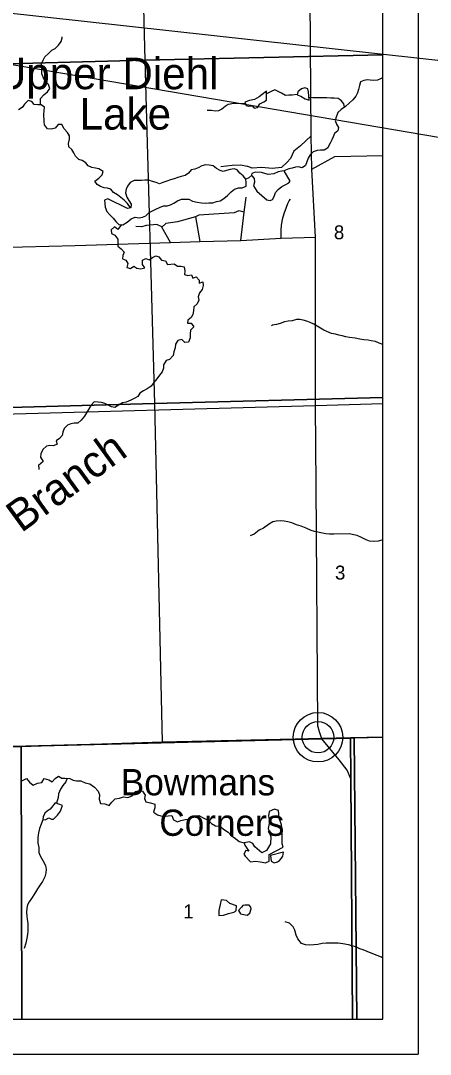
# Model space of a CAD drawing. Extents: x 0 to 34, y 0 to 22.
# Drawn here: x 8.435 to 9.666, y 9.902 to 13.008 of the extents above; entities that cross this region are included whole.
import ezdxf

# ---------------------------------------------------------------- set-up
doc = ezdxf.new("R2010")
doc.units = 0
for name, color, linetype in [('GM_X_Corporation', 7, 'Continuous'), ('GM_X_County_Road', 7, 'Continuous'), ('GM_X_Minor_Lake', 7, 'Continuous'), ('GM_X_Minor_Lake_Text', 7, 'Continuous'), ('GM_X_Minor_River', 7, 'Continuous'), ('GM_X_Minor_River_Text', 7, 'Continuous'), ('GM_X_Section_Text', 7, 'Continuous'), ('GM_X_State_Route', 7, 'Continuous'), ('GM_X_Township_Road', 7, 'Continuous'), ('GM_X_Unincorporated', 7, 'Continuous'), ('GM_X_Unincorporated_Location', 7, 'Continuous'), ('GM_X_Unincorporated_Text', 7, 'Continuous'), ('SH_Data', 7, 'Continuous'), ('SH_Text', 7, 'Continuous')]:
    doc.layers.add(name, color=color, linetype=linetype)

msp = doc.modelspace()

# ---------------------------------------------------------------- linework, layer by layer
at = {"layer": 'GM_X_Corporation'}
msp.add_lwpolyline([(6.7793, 13.0289), (6.7835, 12.8989), (6.7875, 12.7733), (6.7907, 12.6568), (6.7962, 12.4725), (6.8009, 12.313), (6.8013, 12.2922), (6.8061, 11.7851), (6.8093, 11.6831), (6.8339, 10.7907), (7.8767, 10.8135), (8.3328, 10.8251), (9.3392, 10.8506), (9.4256, 10.8527), (9.5231, 10.8551), (9.5231, 15.9621)], dxfattribs=at)
for points in [[(9.5231, 12.905), (9.5231, 13.9277), (8.7817, 13.9109), (8.8081, 12.8893)], [(8.7817, 13.9109), (8.8081, 12.8893), (7.797, 12.8624), (7.775, 13.8905)], [(9.5231, 11.8754), (9.5231, 12.905), (8.8081, 12.8893), (8.8368, 11.8577)], [(8.8081, 12.8893), (8.8368, 11.8577), (7.823, 11.8291), (7.797, 12.8624)], [(9.5231, 10.8546), (9.5231, 11.8754), (8.8368, 11.8577), (8.8598, 10.8393), (9.4367, 10.8525)], [(7.823, 11.8291), (8.8368, 11.8577), (8.8598, 10.8393), (8.4367, 10.8255), (7.8468, 10.813)], [(3.2288, 10.0075), (9.4322, 10.0075), (9.4266, 10.7304), (9.4256, 10.8527), (9.3392, 10.8506), (8.3328, 10.8251), (7.8767, 10.8135), (6.8339, 10.7907), (6.8097, 10.7901), (5.571, 10.7686), (5.2789, 10.7635), (4.6326, 10.7519), (3.2181, 10.7269)], [(8.4382, 10.0075), (9.4449, 10.0075), (9.4367, 10.8525), (8.8598, 10.8393), (8.4367, 10.8255)], [(9.4322, 10.0075), (9.5231, 10.0075), (9.5231, 10.8551), (9.4256, 10.8527), (9.4266, 10.7304)], [(9.4449, 10.0075), (9.5231, 10.0075), (9.5231, 10.8546), (9.4367, 10.8525)], [(7.3462, 10.0075), (8.4382, 10.0075), (8.4367, 10.8255), (7.8468, 10.813), (7.3327, 10.8022)]]:
    msp.add_lwpolyline(points, close=True, dxfattribs=at)
at = {"layer": 'GM_X_County_Road'}
for p, q in [((9.3204, 12.3571), (9.3097, 12.5617)), ((9.5231, 11.8559), (9.321, 11.8505)), ((9.4288, 10.8523), (9.5231, 10.8545))]:
    msp.add_line(p, q, dxfattribs=at)
for points in [[(9.3097, 12.5617), (9.3786, 12.5997), (9.5231, 12.6026)], [(6.8015, 12.2917), (8.4398, 12.3285), (8.5985, 12.3319), (8.8852, 12.3415), (8.9734, 12.3441), (9.0963, 12.3476), (9.2173, 12.3542), (9.3204, 12.3571)], [(9.321, 11.8505), (8.3046, 11.8228), (6.8063, 11.7845)], [(8.333, 10.8245), (9.3394, 10.8501), (9.4258, 10.8522), (9.4288, 10.8523)]]:
    msp.add_lwpolyline(points, dxfattribs=at)
at = {"layer": 'GM_X_Minor_Lake'}
for points in [[(9.2996, 12.7944), (9.2976, 12.8031), (9.2885, 12.8056), (9.2783, 12.8025), (9.2681, 12.7944), (9.2656, 12.7848), (9.2766, 12.7808), (9.2897, 12.773), (9.3015, 12.7689)], [(9.174, 12.7959), (9.1604, 12.7862), (9.1518, 12.7789), (9.1379, 12.7704), (9.1223, 12.7679), (9.1087, 12.7632), (9.1123, 12.7533), (9.1195, 12.7512), (9.1309, 12.7517), (9.1367, 12.7445), (9.1465, 12.7473), (9.1532, 12.758), (9.1653, 12.7642), (9.1739, 12.7685)], [(9.1739, 12.7685), (9.174, 12.7959)], [(9.3015, 12.7689), (9.2996, 12.7944)], [(8.6967, 12.4725), (8.6967, 12.4721), (8.6869, 12.4686), (8.6874, 12.458), (8.6887, 12.4474), (8.6938, 12.4342), (8.7026, 12.4244), (8.7123, 12.4139), (8.7203, 12.4038), (8.7299, 12.3955), (8.7421, 12.3946), (8.7544, 12.4027), (8.7668, 12.412), (8.7788, 12.4175), (8.7906, 12.4157), (8.8004, 12.4177), (8.8106, 12.4209), (8.8207, 12.4309), (8.8308, 12.436), (8.8406, 12.4418), (8.8515, 12.4465), (8.8639, 12.4509), (8.8749, 12.451), (8.8847, 12.4542), (8.8948, 12.4596), (8.9061, 12.4662), (8.9178, 12.4717), (8.9276, 12.4714), (8.9401, 12.4709), (8.9516, 12.4649), (8.9648, 12.4625), (8.9781, 12.4604), (8.9906, 12.4598), (9.0005, 12.4607), (9.0118, 12.4604), (9.0235, 12.464), (9.0348, 12.4664), (9.0449, 12.4738), (9.0566, 12.4819), (9.067, 12.4938), (9.0775, 12.5015), (9.0899, 12.5055), (9.1002, 12.5053), (9.1126, 12.5104), (9.1128, 12.521), (9.1112, 12.5312), (9.1034, 12.5414), (9.0931, 12.5499), (9.0858, 12.5597), (9.0759, 12.5626), (9.0646, 12.5606), (9.0536, 12.5578), (9.0434, 12.5546), (9.0339, 12.5575), (9.0232, 12.5638), (9.0129, 12.5717), (9.0011, 12.5738), (8.9902, 12.5744), (8.9788, 12.5716), (8.9687, 12.5657), (8.9582, 12.5618), (8.9476, 12.5598), (8.939, 12.5494), (8.9289, 12.5428), (8.9176, 12.5393), (8.9066, 12.5364), (8.8965, 12.5329), (8.8852, 12.5293), (8.8739, 12.5254), (8.8618, 12.521), (8.852, 12.5175), (8.8421, 12.5215), (8.8311, 12.524), (8.8201, 12.5281), (8.8079, 12.5287), (8.7974, 12.5278), (8.7871, 12.5273), (8.7754, 12.5271), (8.7637, 12.5216), (8.7563, 12.5109), (8.7515, 12.5014), (8.7502, 12.4903), (8.7542, 12.4771), (8.7596, 12.4669), (8.7666, 12.456), (8.7656, 12.4457), (8.7558, 12.4437)], [(9.227, 12.5563), (9.2198, 12.5551), (9.2085, 12.5534), (9.1953, 12.5475), (9.1787, 12.545), (9.1582, 12.5516), (9.1396, 12.5525), (9.1298, 12.5485), (9.1288, 12.5444), (9.1307, 12.5402), (9.1365, 12.5334), (9.1378, 12.5221), (9.1345, 12.511), (9.1446, 12.4952), (9.1745, 12.4694), (9.1844, 12.4673), (9.1915, 12.4708), (9.1963, 12.4792), (9.201, 12.4918), (9.2089, 12.5006), (9.2201, 12.5099), (9.2318, 12.5157), (9.2408, 12.5208), (9.2445, 12.5254)], [(9.2445, 12.5254), (9.227, 12.5563)], [(8.7558, 12.4437), (8.6967, 12.4725)], [(8.5388, 10.6573), (8.5276, 10.6438), (8.5232, 10.6381), (8.5142, 10.6322), (8.507, 10.6264), (8.5019, 10.6153), (8.5013, 10.6066), (8.51, 10.6075), (8.5194, 10.6126), (8.5271, 10.6081), (8.5335, 10.6082), (8.5451, 10.6206), (8.554, 10.6325), (8.5577, 10.6409), (8.5606, 10.6493)], [(8.5606, 10.6493), (8.5388, 10.6573)], [(9.2232, 10.5238), (9.2211, 10.534), (9.2205, 10.5507), (9.2209, 10.572), (9.2186, 10.5917), (9.2115, 10.6117), (9.21, 10.6345), (9.1978, 10.6384), (9.1816, 10.6309), (9.1799, 10.6188), (9.1821, 10.6002), (9.179, 10.5804), (9.1862, 10.5551), (9.1851, 10.5341), (9.1732, 10.5146), (9.1593, 10.5075), (9.1385, 10.5247), (9.1327, 10.5348), (9.1223, 10.5403), (9.1064, 10.537), (9.1084, 10.5299), (9.1201, 10.5126), (9.1117, 10.514), (9.1058, 10.5036), (9.109, 10.4968), (9.1256, 10.48), (9.1407, 10.4818), (9.1556, 10.4801), (9.1708, 10.4773), (9.1817, 10.4821), (9.1814, 10.5018)], [(9.1814, 10.5018), (9.2232, 10.5238)], [(9.1856, 10.4988), (9.1878, 10.4825), (9.197, 10.4774), (9.2068, 10.4798), (9.2125, 10.4837), (9.2188, 10.491), (9.2225, 10.4968), (9.2242, 10.509)], [(9.2242, 10.509), (9.1856, 10.4988)], [(9.0833, 10.3479), (9.0635, 10.3548), (9.0531, 10.3641), (9.0371, 10.3661), (9.0339, 10.3516), (9.0308, 10.3337), (9.0299, 10.3189), (9.044, 10.3203), (9.0594, 10.3251), (9.0757, 10.3288)], [(9.0834, 10.3479), (9.0635, 10.3548), (9.0531, 10.3641), (9.0371, 10.3661), (9.0339, 10.3516), (9.0308, 10.3337), (9.0299, 10.3189), (9.044, 10.3203), (9.0594, 10.3251), (9.0757, 10.3288)], [(9.0757, 10.3288), (9.0798, 10.3312), (9.0825, 10.3337), (9.0833, 10.3479)], [(9.0982, 10.3443), (9.0897, 10.3343), (9.0952, 10.3234), (9.1153, 10.3195), (9.1236, 10.3254), (9.1279, 10.3387), (9.1267, 10.344), (9.1213, 10.3496)], [(9.1213, 10.3496), (9.1081, 10.3499), (9.1029, 10.3491), (9.0982, 10.3443)]]:
    msp.add_lwpolyline(points, dxfattribs=at)
at = {"layer": 'GM_X_Minor_River'}
for points in [[(8.494, 12.7549), (8.4948, 12.7735), (8.5041, 12.7846), (8.515, 12.7935), (8.5224, 12.8035), (8.5181, 12.8159), (8.5073, 12.8272), (8.5023, 12.8381), (8.4987, 12.8483), (8.4982, 12.8585), (8.498, 12.8684), (8.4975, 12.8783), (8.5019, 12.8893), (8.5071, 12.8993), (8.5183, 12.9093), (8.5284, 12.9189), (8.5385, 12.9244), (8.5486, 12.9344), (8.5564, 12.9451), (8.5593, 12.9558), (8.5592, 12.9592)], [(9.5231, 12.8374), (9.5166, 12.8331), (9.5068, 12.8288), (9.4966, 12.8276), (9.4856, 12.8289), (9.476, 12.8303), (9.4662, 12.8283), (9.4556, 12.8244), (9.4531, 12.813), (9.4499, 12.8008), (9.4466, 12.7908), (9.4421, 12.7813), (9.4335, 12.7698), (9.4223, 12.7602), (9.411, 12.7498), (9.3979, 12.7409), (9.3881, 12.7316), (9.383, 12.7175), (9.3801, 12.708), (9.3836, 12.697), (9.3898, 12.6868), (9.388, 12.6769), (9.3783, 12.6684), (9.3735, 12.6589), (9.3702, 12.6493), (9.3654, 12.6394), (9.3564, 12.6245), (9.3466, 12.619), (9.336, 12.6185), (9.3258, 12.6173), (9.3137, 12.6137), (9.3047, 12.6041), (9.2991, 12.5941), (9.2947, 12.5834), (9.2907, 12.5728), (9.2805, 12.5658), (9.2702, 12.5683), (9.2607, 12.5678), (9.2505, 12.5647), (9.2407, 12.5623), (9.2309, 12.5587), (9.2271, 12.5562)], [(9.2659, 12.7859), (9.2504, 12.7835), (9.2405, 12.7842), (9.2307, 12.7829), (9.2188, 12.7896), (9.1982, 12.7996), (9.1877, 12.7945), (9.174, 12.7879)], [(8.7645, 12.4455), (8.7555, 12.4585), (8.7463, 12.4683), (8.7356, 12.4765), (8.7257, 12.4843), (8.7138, 12.4917), (8.7057, 12.5015), (8.6958, 12.5044), (8.6852, 12.5058), (8.6742, 12.5098), (8.6646, 12.5158), (8.6577, 12.5259), (8.6693, 12.5348), (8.6798, 12.544), (8.6823, 12.5543), (8.6693, 12.5625), (8.6598, 12.5643), (8.6488, 12.5668), (8.6377, 12.5712), (8.6304, 12.581), (8.6193, 12.5876), (8.6095, 12.5905), (8.5999, 12.6003), (8.5944, 12.6108), (8.589, 12.6206), (8.5794, 12.6289), (8.5789, 12.6391), (8.5817, 12.6513), (8.582, 12.6615), (8.5754, 12.6717), (8.5658, 12.6826), (8.558, 12.6961), (8.5474, 12.6956), (8.5381, 12.6849), (8.5264, 12.6817), (8.515, 12.683), (8.5065, 12.6947), (8.5053, 12.7049), (8.5042, 12.7262), (8.5052, 12.7379), (8.5062, 12.7478), (8.4966, 12.7549), (8.486, 12.7548), (8.4758, 12.7554), (8.4681, 12.7651), (8.4574, 12.7677), (8.4458, 12.7573), (8.4388, 12.7465), (8.4287, 12.7396)], [(9.4078, 12.7476), (9.406, 12.7581), (9.3983, 12.7678), (9.3887, 12.7742), (9.3769, 12.7748), (9.3671, 12.7751), (9.3549, 12.7757), (9.345, 12.7763), (9.3355, 12.7754), (9.3238, 12.7757), (9.3124, 12.7763), (9.3009, 12.7766)], [(9.1103, 12.7587), (9.0963, 12.7577), (9.0856, 12.7587), (9.0754, 12.759), (9.0587, 12.7557), (9.0489, 12.7495), (9.0392, 12.7418), (9.029, 12.7364), (9.0191, 12.7363), (9.0081, 12.7376), (8.9986, 12.7379), (8.9956, 12.7379)], [(9.1291, 12.5437), (9.1203, 12.535), (9.1112, 12.5312)], [(8.7381, 12.3949), (8.7264, 12.3807), (8.7168, 12.3882), (8.7071, 12.3793), (8.708, 12.3683), (8.7179, 12.3631), (8.7268, 12.3511), (8.7265, 12.3405), (8.7267, 12.3302), (8.7366, 12.322), (8.7462, 12.3123), (8.7418, 12.3023), (8.7405, 12.2917), (8.7511, 12.288), (8.7566, 12.2782), (8.7537, 12.2661), (8.7647, 12.2632), (8.7745, 12.2697), (8.784, 12.2638), (8.7962, 12.2617), (8.8075, 12.2653), (8.8013, 12.2754), (8.8011, 12.2876), (8.8112, 12.293), (8.8208, 12.2886), (8.8305, 12.2959), (8.8407, 12.3014), (8.8502, 12.2985), (8.8579, 12.2883), (8.8704, 12.2858), (8.8759, 12.2753), (8.8864, 12.2758), (8.8963, 12.2771), (8.9062, 12.27), (8.9161, 12.2697), (8.9259, 12.2684), (8.928, 12.2555), (8.9274, 12.2448), (8.9369, 12.2416), (8.9479, 12.2436), (8.9522, 12.2338), (8.9623, 12.2377), (8.9708, 12.228), (8.9713, 12.2185), (8.9822, 12.2228), (8.9831, 12.2118), (8.9803, 12.2), (8.9724, 12.1904), (8.9677, 12.1782), (8.9701, 12.168), (8.965, 12.1569), (8.9553, 12.1477), (8.9539, 12.1359), (8.9525, 12.1252), (8.947, 12.1153), (8.9373, 12.108), (8.9359, 12.0984), (8.9469, 12.0986), (8.955, 12.0881), (8.9449, 12.0773), (8.9439, 12.0671), (8.9437, 12.0545), (8.9389, 12.0416), (8.9284, 12.0403), (8.9188, 12.05), (8.9071, 12.0464), (8.9, 12.0361), (8.8987, 12.0247), (8.8947, 12.0125), (8.8933, 12.0011), (8.8825, 11.9899), (8.872, 11.9864), (8.8638, 11.9734), (8.8643, 11.9639), (8.8603, 11.9528), (8.8518, 11.9421), (8.844, 11.931), (8.835, 11.9202), (8.8272, 11.9099), (8.8152, 11.9014), (8.8043, 11.8955), (8.7927, 11.8885), (8.7872, 11.8782), (8.7755, 11.8727), (8.7657, 11.8677), (8.7514, 11.8618), (8.7409, 11.859), (8.7288, 11.8528), (8.718, 11.8458), (8.7077, 11.8472), (8.6974, 11.8527), (8.6875, 11.8571), (8.6772, 11.8604), (8.6674, 11.8618), (8.6553, 11.862), (8.6459, 11.8517), (8.6389, 11.839), (8.633, 11.8291), (8.6263, 11.8195), (8.617, 11.8072), (8.6066, 11.7987)], [(9.5231, 12.0351), (9.5125, 12.039), (9.5015, 12.0434), (9.4882, 12.0455), (9.4787, 12.0473), (9.4662, 12.0482), (9.4537, 12.0503), (9.4396, 12.0532), (9.4229, 12.056), (9.4116, 12.0577), (9.4009, 12.0603), (9.391, 12.0628), (9.3808, 12.0653), (9.369, 12.0682), (9.3553, 12.0733), (9.3458, 12.0774), (9.3359, 12.0841), (9.3263, 12.0896), (9.3156, 12.0956), (9.3046, 12.1007), (9.2947, 12.1051), (9.284, 12.108), (9.2738, 12.1102), (9.2636, 12.1093), (9.2511, 12.1061), (9.239, 12.1052), (9.2277, 12.1027), (9.2149, 12.098), (9.2036, 12.0948), (9.1919, 12.0924), (9.1881, 12.0908)], [(8.6066, 11.7987), (8.596, 11.7982), (8.5854, 11.7962), (8.5756, 11.7923), (8.5655, 11.7826), (8.5615, 11.7716), (8.5598, 11.7617), (8.5519, 11.7521), (8.5418, 11.7455), (8.5442, 11.7349), (8.5333, 11.7298), (8.5219, 11.7312), (8.5121, 11.7292), (8.5017, 11.7195), (8.4954, 11.7065), (8.4948, 11.6963), (8.5026, 11.6831), (8.4883, 11.6715), (8.4892, 11.6617), (8.4896, 11.659)], [(9.5231, 11.448), (9.5204, 11.4467), (9.5094, 11.4438), (9.4938, 11.4428), (9.4828, 11.4434), (9.4729, 11.4478), (9.4595, 11.4548), (9.4457, 11.4606), (9.4362, 11.4631), (9.4217, 11.4656), (9.3758, 11.4648), (9.3629, 11.4646), (9.3515, 11.4656), (9.3416, 11.4677), (9.318, 11.4726), (9.308, 11.4759), (9.2931, 11.4825), (9.2782, 11.4883), (9.2641, 11.493), (9.25, 11.4985), (9.2374, 11.5021), (9.2267, 11.5038), (9.2142, 11.5043), (9.2028, 11.5034), (9.1926, 11.5013), (9.1798, 11.4935), (9.1641, 11.4826), (9.1516, 11.4764), (9.1366, 11.4651), (9.1246, 11.4596)], [(8.4382, 10.7233), (8.4525, 10.7307), (8.4611, 10.7191), (8.4722, 10.7109), (8.4858, 10.7161), (8.4979, 10.7189), (8.5053, 10.7308), (8.5194, 10.7269), (8.529, 10.7202), (8.5383, 10.731), (8.5485, 10.738), (8.5581, 10.7313), (8.5676, 10.7315), (8.5824, 10.7306), (8.5923, 10.7254), (8.6026, 10.7237), (8.6159, 10.7235), (8.6289, 10.7173), (8.6422, 10.7148), (8.6565, 10.7041), (8.6677, 10.6921), (8.672, 10.6815), (8.6703, 10.6682), (8.6747, 10.6557), (8.6873, 10.6548), (8.701, 10.6489), (8.7092, 10.6597), (8.7189, 10.669), (8.7318, 10.6711), (8.7439, 10.6759), (8.7572, 10.6734), (8.77, 10.6789), (8.7812, 10.6917), (8.7918, 10.6949), (8.8013, 10.692), (8.8087, 10.6807), (8.8073, 10.6708), (8.8109, 10.6602), (8.8247, 10.6574), (8.8376, 10.6531), (8.8378, 10.6421), (8.8342, 10.6295), (8.8458, 10.6209), (8.8557, 10.6184), (8.8652, 10.6171), (8.8781, 10.618), (8.8894, 10.619), (8.8938, 10.6058), (8.9061, 10.6003), (8.9159, 10.6046), (8.9303, 10.6071), (8.9405, 10.6088), (8.957, 10.6186), (8.9703, 10.6191), (8.9852, 10.611), (8.9986, 10.6048), (9.0079, 10.5951), (9.0205, 10.5881), (9.0331, 10.5868), (9.0473, 10.5767), (9.0584, 10.5689), (9.0673, 10.5588), (9.0808, 10.5507), (9.0912, 10.541), (9.1064, 10.537)], [(8.5745, 10.7311), (8.5704, 10.7201), (8.5615, 10.7097), (8.5541, 10.6982), (8.5482, 10.6848), (8.5473, 10.6738), (8.542, 10.6561)], [(8.5013, 10.6066), (8.4915, 10.5802), (8.4883, 10.5669), (8.4859, 10.5528), (8.4861, 10.5357), (8.4898, 10.5228), (8.4896, 10.508), (8.4932, 10.4982), (8.5018, 10.4843), (8.5093, 10.4692), (8.5117, 10.4575), (8.5108, 10.4472), (8.5072, 10.4346), (8.5002, 10.4212), (8.4931, 10.4108), (8.4857, 10.3989), (8.4761, 10.384), (8.4669, 10.3701), (8.4602, 10.3601), (8.4554, 10.3506), (8.4533, 10.341), (8.4524, 10.3281), (8.4533, 10.3167), (8.4542, 10.3065), (8.4563, 10.2955), (8.4565, 10.2834), (8.4563, 10.2716), (8.4554, 10.2621), (8.4537, 10.2503), (8.4501, 10.2354), (8.4451, 10.2194)], [(9.5231, 10.1907), (9.5187, 10.1932), (9.5057, 10.1983), (9.4927, 10.2034), (9.4766, 10.2111), (9.4644, 10.2155), (9.4537, 10.2191), (9.4438, 10.2235), (9.4308, 10.2278), (9.4205, 10.2307), (9.403, 10.2338), (9.3885, 10.2355), (9.3775, 10.2357), (9.3661, 10.2359), (9.3525, 10.2357), (9.3407, 10.2343), (9.3275, 10.2318), (9.3161, 10.2305), (9.3032, 10.2295), (9.2911, 10.2309), (9.2792, 10.2349), (9.2676, 10.2483), (9.2629, 10.2597), (9.2592, 10.2744), (9.2541, 10.285), (9.2425, 10.2954), (9.2292, 10.3001)]]:
    msp.add_lwpolyline(points, dxfattribs=at)
at = {"layer": 'GM_X_State_Route'}
for p, q in [((9.3069, 12.7953), (9.3018, 13.3591)), ((9.3204, 12.3571), (9.3097, 12.5617)), ((9.3209, 11.9796), (9.3204, 12.3571))]:
    msp.add_line(p, q, dxfattribs=at)
for points in [[(9.3097, 12.5617), (9.3081, 12.662), (9.3069, 12.7953)], [(9.3228, 11.6123), (9.321, 11.8505), (9.3209, 11.9796)], [(9.3394, 10.8501), (9.3326, 10.8707), (9.3282, 10.8889), (9.3228, 11.6123)], [(9.4324, 10.0075), (9.4268, 10.7298), (9.4159, 10.7551), (9.3915, 10.787), (9.3394, 10.8501)]]:
    msp.add_lwpolyline(points, dxfattribs=at)
at = {"layer": 'GM_X_Township_Road'}
msp.add_line((8.9599, 12.4182), (8.9734, 12.3441), dxfattribs=at)
for points in [[(9.3081, 12.662), (9.2758, 12.6314), (9.2558, 12.6156), (9.2454, 12.5936), (9.2348, 12.5811), (9.2189, 12.5662), (9.1902, 12.5634), (9.1593, 12.5663), (9.1309, 12.5647), (9.1171, 12.5693)], [(9.1171, 12.5693), (9.1152, 12.5699), (9.0965, 12.5735), (9.0703, 12.5728), (9.0363, 12.5687)], [(9.0963, 12.3476), (9.1069, 12.4326), (9.1126, 12.4778)], [(9.2173, 12.3542), (9.2173, 12.3788), (9.2186, 12.392), (9.2221, 12.411), (9.2268, 12.4282), (9.234, 12.447), (9.2377, 12.4586), (9.2419, 12.4668), (9.2456, 12.4713)], [(9.1069, 12.4326), (9.0902, 12.4361), (9.076, 12.4307), (8.9703, 12.4229), (8.9599, 12.4182), (8.9056, 12.4031), (8.8712, 12.3987), (8.8588, 12.3868)], [(8.8852, 12.3415), (8.8588, 12.3868), (8.8574, 12.3891), (8.8439, 12.3956), (8.8133, 12.392), (8.7975, 12.3885), (8.7804, 12.3891)]]:
    msp.add_lwpolyline(points, dxfattribs=at)
at = {"layer": 'GM_X_Unincorporated'}
for radius in [0.0744, 0.0472]:
    msp.add_circle((9.3284, 10.8546), radius, dxfattribs=at)
at = {"layer": 'GM_X_Unincorporated_Location'}
msp.add_line((9.3284, 10.8546), (9.3284, 10.8546), dxfattribs=at)
at = {"layer": 'SH_Data'}
for p in [(9.6297, 16.9017), (2.6297, 9.9017)]:
    msp.add_line(p, (9.6297, 9.9017), dxfattribs=at)
at = {"layer": 'SH_Text'}
msp.add_lwpolyline([(10.1431, 12.8377), (5.8618, 13.3103), (10.1431, 12.581)], close=True, dxfattribs=at)

# ---------------------------------------------------------------- texts
at = {"layer": 'GM_X_Minor_Lake_Text'}
for s, height, rotation, p in [('Upper Diehl', 0.094732, 359.9569, (8.3602, 12.802)), ('Lake', 0.09473, 359.9568, (8.6121, 12.6805))]:
    msp.add_text(s, height=height, rotation=rotation, dxfattribs=at).set_placement(p)
at = {"layer": 'GM_X_Minor_River_Text'}
msp.add_text('Branch', height=0.09473, rotation=35.9921, dxfattribs=at).set_placement((8.4364, 11.467))
at = {"layer": 'GM_X_Section_Text'}
for s, p in [('8', (9.3761, 12.3508)), ('3', (9.3794, 11.3283)), ('1', (8.9232, 10.31))]:
    msp.add_text(s, height=0.0419, rotation=0, dxfattribs=at).set_placement(p)
at = {"layer": 'GM_X_Unincorporated_Text'}
for s, p in [('Bowmans', (8.7357, 10.6799)), ('Corners', (8.8515, 10.5582))]:
    msp.add_text(s, height=0.07898, rotation=0, dxfattribs=at).set_placement(p)

doc.saveas('drawing.dxf')
